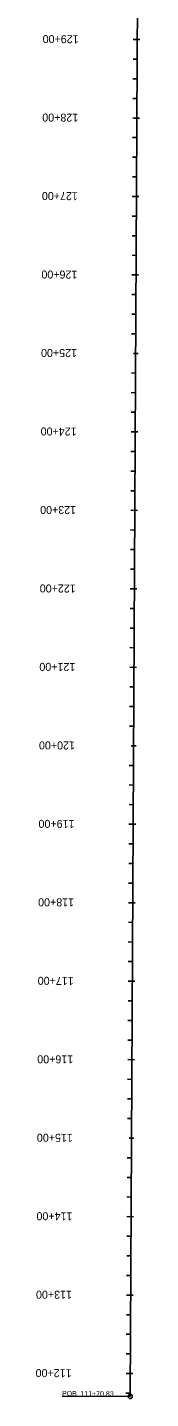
# Model space of a CAD drawing. Extents: x 17535628 to 17537899, y 7333852 to 7342653.
# Drawn here: x 17535628 to 17535763, y 7333852 to 7335599 of the extents above; entities that cross this region are included whole.
import ezdxf

# ---------------------------------------------------------------- set-up
doc = ezdxf.new("R2010")
doc.units = 0
for name, color, linetype in [('Alignment', 7, 'Continuous'), ('TextAlignment', 7, 'Continuous'), ('TextAlignmentLrg', 7, 'Continuous'), ('TextAlignmentSml', 7, 'Continuous')]:
    doc.layers.add(name, color=color, linetype=linetype)

msp = doc.modelspace()

# ---------------------------------------------------------------- linework, layer by layer
at = {"layer": 'Alignment'}
msp.add_line((17535748.4, 7333854.2), (17535763.4, 7336680.4), dxfattribs=at)
at = {"layer": 'TextAlignment'}
msp.add_line((17535748.4, 7333854.2), (17535661.4, 7333854.6), dxfattribs=at)
msp.add_circle((17535748.4, 7333854.2), 2.67, dxfattribs=at)
at = {"layer": 'TextAlignmentLrg'}
for p, q in [((17535757.6, 7335583.3), (17535752.1, 7335583.4)), ((17535757.1, 7335483.3), (17535751.6, 7335483.4)), ((17535756.5, 7335383.3), (17535751.1, 7335383.4)), ((17535756, 7335283.3), (17535750.5, 7335283.4)), ((17535752.4, 7335183.4), (17535758.5, 7335183.3)), ((17535754.9, 7335083.3), (17535749.5, 7335083.4)), ((17535754.4, 7334983.3), (17535749, 7334983.4)), ((17535753.9, 7334883.3), (17535748.4, 7334883.4)), ((17535753.4, 7334783.3), (17535747.9, 7334783.4)), ((17535749.8, 7334683.4), (17535755.9, 7334683.3)), ((17535752.3, 7334583.3), (17535746.8, 7334583.4)), ((17535751.8, 7334483.3), (17535746.3, 7334483.4)), ((17535751.2, 7334383.3), (17535745.8, 7334383.4)), ((17535750.7, 7334283.3), (17535745.2, 7334283.4)), ((17535747.1, 7334183.4), (17535753.2, 7334183.3)), ((17535749.6, 7334083.3), (17535744.2, 7334083.4)), ((17535749.1, 7333983.4), (17535743.6, 7333983.4)), ((17535748.6, 7333883.4), (17535743.1, 7333883.4))]:
    msp.add_line(p, q, dxfattribs=at)
at = {"layer": 'TextAlignmentSml'}
for p, q in [((17535754.5, 7335583.3), (17535760.7, 7335583.3)), ((17535757.5, 7335558.3), (17535752, 7335558.4)), ((17535757.3, 7335533.3), (17535751.9, 7335533.4)), ((17535757.2, 7335508.3), (17535751.7, 7335508.4)), ((17535754, 7335483.3), (17535760.1, 7335483.3)), ((17535756.9, 7335458.3), (17535751.5, 7335458.4)), ((17535756.8, 7335433.3), (17535751.3, 7335433.4)), ((17535756.7, 7335408.3), (17535751.2, 7335408.4)), ((17535753.5, 7335383.3), (17535759.6, 7335383.3)), ((17535756.4, 7335358.3), (17535750.9, 7335358.4)), ((17535756.3, 7335333.3), (17535750.8, 7335333.4)), ((17535756.1, 7335308.3), (17535750.7, 7335308.4)), ((17535752.9, 7335283.3), (17535759.1, 7335283.3)), ((17535755.9, 7335258.3), (17535750.4, 7335258.4)), ((17535755.7, 7335233.3), (17535750.3, 7335233.4)), ((17535755.6, 7335208.3), (17535750.2, 7335208.4)), ((17535752.4, 7335183.4), (17535758.5, 7335183.3)), ((17535755.3, 7335158.3), (17535749.9, 7335158.4)), ((17535755.2, 7335133.3), (17535749.8, 7335133.4)), ((17535755.1, 7335108.3), (17535749.6, 7335108.4)), ((17535751.9, 7335083.4), (17535758, 7335083.3)), ((17535754.8, 7335058.3), (17535749.4, 7335058.4)), ((17535754.7, 7335033.3), (17535749.2, 7335033.4)), ((17535754.5, 7335008.3), (17535749.1, 7335008.4)), ((17535751.4, 7334983.4), (17535757.5, 7334983.3)), ((17535754.3, 7334958.3), (17535748.8, 7334958.4)), ((17535754.2, 7334933.3), (17535748.7, 7334933.4)), ((17535754, 7334908.3), (17535748.6, 7334908.4)), ((17535750.8, 7334883.4), (17535756.9, 7334883.3)), ((17535753.8, 7334858.3), (17535748.3, 7334858.4)), ((17535753.6, 7334833.3), (17535748.2, 7334833.4)), ((17535753.5, 7334808.3), (17535748, 7334808.4)), ((17535750.3, 7334783.4), (17535756.4, 7334783.3)), ((17535753.2, 7334758.3), (17535747.8, 7334758.4)), ((17535753.1, 7334733.3), (17535747.6, 7334733.4)), ((17535753, 7334708.3), (17535747.5, 7334708.4)), ((17535749.8, 7334683.4), (17535755.9, 7334683.3)), ((17535752.7, 7334658.3), (17535747.2, 7334658.4)), ((17535752.6, 7334633.3), (17535747.1, 7334633.4)), ((17535752.4, 7334608.3), (17535747, 7334608.4)), ((17535749.2, 7334583.4), (17535755.4, 7334583.3)), ((17535752.2, 7334558.3), (17535746.7, 7334558.4)), ((17535752, 7334533.3), (17535746.6, 7334533.4)), ((17535751.9, 7334508.3), (17535746.4, 7334508.4)), ((17535748.7, 7334483.4), (17535754.8, 7334483.3)), ((17535751.6, 7334458.3), (17535746.2, 7334458.4)), ((17535751.5, 7334433.3), (17535746, 7334433.4)), ((17535751.4, 7334408.3), (17535745.9, 7334408.4)), ((17535748.2, 7334383.4), (17535754.3, 7334383.3)), ((17535751.1, 7334358.3), (17535745.6, 7334358.4)), ((17535751, 7334333.3), (17535745.5, 7334333.4)), ((17535750.8, 7334308.3), (17535745.4, 7334308.4)), ((17535747.6, 7334283.4), (17535753.8, 7334283.3)), ((17535750.6, 7334258.3), (17535745.1, 7334258.4)), ((17535750.4, 7334233.3), (17535745, 7334233.4)), ((17535750.3, 7334208.3), (17535744.8, 7334208.4)), ((17535747.1, 7334183.4), (17535753.2, 7334183.3)), ((17535750, 7334158.3), (17535744.6, 7334158.4)), ((17535749.9, 7334133.3), (17535744.4, 7334133.4)), ((17535749.8, 7334108.3), (17535744.3, 7334108.4)), ((17535746.6, 7334083.4), (17535752.7, 7334083.3)), ((17535749.5, 7334058.4), (17535744, 7334058.4)), ((17535749.4, 7334033.4), (17535743.9, 7334033.4)), ((17535749.2, 7334008.4), (17535743.8, 7334008.4)), ((17535746, 7333983.4), (17535752.2, 7333983.3)), ((17535749, 7333958.4), (17535743.5, 7333958.4)), ((17535748.8, 7333933.4), (17535743.4, 7333933.4)), ((17535748.7, 7333908.4), (17535743.2, 7333908.4)), ((17535745.5, 7333883.4), (17535751.6, 7333883.3)), ((17535748.4, 7333858.4), (17535743, 7333858.4))]:
    msp.add_line(p, q, dxfattribs=at)

# ---------------------------------------------------------------- texts
at = {"layer": 'TextAlignment'}
for s, p in [('POB ', (17535661.4, 7333854.8)), ('111+70.83', (17535684.8, 7333854.6))]:
    msp.add_text(s, height=6.48, rotation=359.6959, dxfattribs=at).set_placement(p)
at = {"layer": 'TextAlignmentLrg'}
for s, p in [('125+00', (17535680.5, 7335188.8)), ('120+00', (17535677.9, 7334688.8)), ('115+00', (17535675.2, 7334188.8))]:
    msp.add_text(s, height=10.2, rotation=179.6959, dxfattribs=at).set_placement(p)
at = {"layer": 'TextAlignmentSml'}
for s, p in [('129+00', (17535682.6, 7335588.8)), ('128+00', (17535682.1, 7335488.8)), ('127+00', (17535681.6, 7335388.8)), ('126+00', (17535681, 7335288.8)), ('125+00', (17535680.5, 7335188.8)), ('124+00', (17535680, 7335088.8)), ('123+00', (17535679.4, 7334988.8)), ('122+00', (17535678.9, 7334888.8)), ('121+00', (17535678.4, 7334788.8)), ('120+00', (17535677.9, 7334688.8)), ('119+00', (17535677.3, 7334588.8)), ('118+00', (17535676.8, 7334488.8)), ('117+00', (17535676.3, 7334388.8)), ('116+00', (17535675.7, 7334288.8)), ('115+00', (17535675.2, 7334188.8)), ('114+00', (17535674.7, 7334088.8)), ('113+00', (17535674.1, 7333988.8)), ('112+00', (17535673.6, 7333888.9))]:
    msp.add_text(s, height=10.2, rotation=179.6959, dxfattribs=at).set_placement(p)

doc.saveas('drawing.dxf')
